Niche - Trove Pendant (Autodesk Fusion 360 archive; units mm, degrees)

design "Trove" references "Niche - Chief Architect - Luxe Single Pendant Cordset", "Luxe Single Pendant Cordset - 4ft Standard", "Trove"
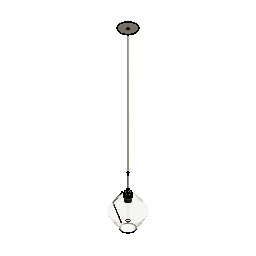
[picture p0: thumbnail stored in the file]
external_derived "ExternalDerived1" bodies "Trove"
external_derived "ExternalDerived2" bodies "Socket Body", "Shade Ring", "Shade Ring +Collar", "Socket", "Body1", "Metal Strain Relief", "Fabric Cord (1)", "Stem (Threaded)"
align "Align1"
external_derived "ExternalDerived3" bodies "T9-Bulb"
move "Move1"
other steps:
derived_base_feature "Derived Base Feature1" bodies "Trove"
derived_base_feature "Derived Base Feature2" bodies "Socket Body", "Shade Ring", "Shade Ring +Collar", "Socket", "Body1", "Metal Strain Relief", "Fabric Cord (1)", "Stem (Threaded)"
derived_base_feature "Derived Base Feature3" bodies "T9-Bulb"
named bodies: "Trove", "Socket Body", "Shade Ring", "Shade Ring +Collar", "Socket", "Body1", "Metal Strain Relief", "Fabric Cord (1)", "Stem (Threaded)", "Cap (Threaded)", "5M Set Screw", "T9-Bulb"

design "Luxe Single Pendant Cordset - 4ft Standard" references "Luxe Canopy - Single Pendant Cordset"
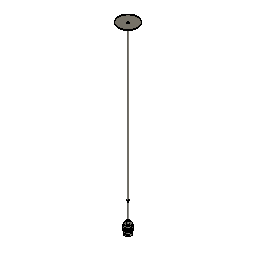
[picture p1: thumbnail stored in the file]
external_derived "ExternalDerived2" bodies "Cap (Threaded)"
move "Move1"
move "Move2"
offset_faces "OffsetFaces1" distance 1051.56
move "Move3"
move "Move4"
move "Move5"
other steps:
derived_base_feature "Derived Base Feature9" bodies "Socket Body", "Shade Ring", "Shade Ring +Collar", "Socket"
derived_base_feature "Derived Base Feature10" bodies "Body1"
derived_base_feature "Derived Base Feature12" bodies "Metal Strain Relief"
derived_base_feature "Derived Base Feature13" bodies "Fabric Cord (1)"
derived_base_feature "Derived Base Feature14" bodies "Stem (Threaded)"
derived_base_feature "Derived Base Feature15" bodies "Cap 9Threaded)", "Cap (Threaded)"
named bodies: "Socket Body", "Shade Ring", "Shade Ring +Collar", "Socket", "Metal Strain Relief", "Fabric Cord (1)", "Stem (Threaded)", "Cap 9Threaded)", "Body1", "Cap (Threaded)", "5M Set Screw"

design "Luxe Canopy - Single Pendant Cordset" references "M5 Set Screw", "Canopy Mounting Bar", "Plastic Strain Relief", "Canopy Mounting Bar Screw", "Luxe Cordset"
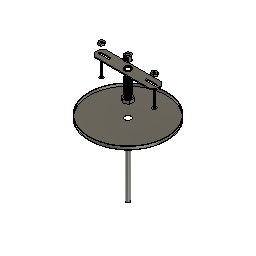
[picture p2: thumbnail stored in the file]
sketch "Sketch1" plane through (0, 0, 0) normal (0, 0, 1) x axis (1, 0, 0)
  circle C1 centre (0, 0) radius 63.5
  point P1 (0, 0)
  point P2 (0, 0)
  coincident P1 P2
  dimension "d1" diameter C1 = 127
extrude "Extrude1" new body sketch "Sketch1" along normal blind 5.08
shell "Shell1" innerThickness 0.762
hole "Hole1" HoleDepth 35.56 HoleDiameter 10.16 TipAngle 118
component_from_bodies "Body->Comp1"
component_insert "Component Insert1"
component_insert "Component Insert2"
component_insert "Component Insert3"
sketch "Sketch2" plane through (0, 0, 0) normal (0, 0, 1) x axis (1, 0, 0)
  circle C1 centre (0, 0) radius 3.175
  point P1 (0, 0)
  point P2 (0, 0)
  coincident P1 P2
  dimension "d8" diameter C1 = 6.35
extrude "Extrude2" new body sketch "Sketch2" along normal blind 127 and against normal blind 127 bodies "Fabric Cord"
component_insert "Component Insert4"
component_insert "Component Insert5"
position "Position1"
sketch "Sketch3" plane through (0, 0, 0.762) normal (0, 0, 1) x axis (-1, 0, 0)
  circle C1 centre (-0.0475, 0.2257) radius 5.08
  circle C2 centre (0, 0) radius 62.738
  circle C3 centre (0, 0) radius 4.826
  concentric C2 C3
  dimension "d13" diameter C3 = 9.652
extrude "Extrude3" new body sketch "Sketch3" profile of C3 along normal blind 25.4 bodies "Threaded Nipple"
shell "Shell2" innerThickness 1.27
thread "Thread1"
sketch "Sketch5" plane through (0, 0, 127) normal (0, 0, 1) x axis (-1, 0, 0)
  line L1 (-6.8191, 3.937) -> (0, 7.874)
  line L2 (-6.8191, -3.937) -> (-6.8191, 3.937)
  line L3 (0, -7.874) -> (-6.8191, -3.937)
  line L4 (6.8191, -3.937) -> (0, -7.874)
  line L5 (6.8191, 3.937) -> (6.8191, -3.937)
  line L6 (0, 7.874) -> (6.8191, 3.937)
  circle C1 centre (0, 0) radius 3.175
  point P2 (0, 0)
  point P9 (0, 0)
  point P3 (0, 7.874)
  coincident P2 P9
  dimension "d20" distance P3 P9 = 7.874
extrude "Extrude4" new body sketch "Sketch5" along normal blind 5.08 bodies "Hex Nut"
move "Move1"
thread "Thread2"
move "Move2" TranslateX 0 TranslateY 0 TranslateZ -55.88
move "Move3" TranslateX 0 TranslateY 0 TranslateZ 60.96
position "Position2"
sketch "Sketch6" plane through (0, 0, 0) normal (0, 0, 1) x axis (1, 0, 0)
  circle C1 centre (0, 0) radius 9.525
  point P1 (0, 0)
  point P2 (0, 0)
  coincident P1 P2
  dimension "d29" diameter C1 = 19.05
extrude "Extrude5" new body sketch "Sketch6" along normal blind 16.129 bodies "Metal Strain Relief"
move "Move4" TranslateX 0 TranslateY 0 TranslateZ -86.36
hole "Hole2" HoleDepth 10.16 HoleDiameter 5.08 TipAngle 118
hole "Hole3" HoleDepth 4.064 HoleDiameter 7.62 TipAngle 180
hole "Hole4" HoleDepth 12.192 HoleDiameter 9.144 TipAngle 180
thread "Thread3" ThreadOffset 0 ThreadLength 6.096
move "Move1" TranslateX 0 TranslateY 0 TranslateZ 68.58
move "Move5" TranslateX 0 TranslateY 0 TranslateZ 138.43
component_insert "Component Insert6"
external_derived "ExternalDerived1" bodies "5M Set Screw"
move "Move6" TranslateX 0 TranslateY 0 TranslateZ -185.42
copy_paste_bodies "CopyPasteBodies1"
move "Move7" TranslateX 0 TranslateY 0 TranslateZ -12.7
offset_faces "OffsetFaces1" distance -152.4
move "Move8"
component_from_bodies "Body->Comp2"
component_from_bodies "Body->Comp3"
component_from_bodies "Body->Comp4"
component_from_bodies "Body->Comp5"
hole "Hole1" HoleDepth 25.4 HoleDiameter 6.35 TipAngle 180
sketch "Sketch7" plane through (0, 0, 0) normal (0, 0, 1) x axis (1, 0, 0)
  line L1 (49.784, 3.9595) -> (52.07, 0)
  line L2 (45.212, 3.9595) -> (49.784, 3.9595)
  line L3 (42.926, 0) -> (45.212, 3.9595)
  line L4 (45.212, -3.9595) -> (42.926, 0)
  line L5 (49.784, -3.9595) -> (45.212, -3.9595)
  line L6 (52.07, 0) -> (49.784, -3.9595)
  point P2 (52.07, 0)
  point P8 (47.498, 0)
  dimension "d63" distance P2 P8 = 4.572
extrude "Extrude6" new body sketch "Sketch7" along normal blind 3.175 bodies "Mounting Hex Nut"
hole "Hole5" HoleDepth 25.4 HoleDiameter 3.81 TipAngle 180
thread "Thread4"
move "Move9"
component_from_bodies "Body->Comp6"
copy_paste "CopyPaste1"
move "Move10"
derived_base_feature "Derived Base Feature3" bodies "Stem (Threaded)", "Cap 9Threaded)"
move "Move11"
component_from_bodies "Body->Comp7"
component_from_bodies "Body->Comp8"
component_from_bodies "Body->Comp9"
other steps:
base_feature "Base Feature1"
base_feature "Base Feature1" bodies "Stem (Threaded)"
base_feature "Base Feature1" bodies "Cap 9Threaded)"
base_feature "Base Feature1" bodies "Fabric Cord"
base_feature "Base Feature1" bodies "Metal Strain Relief"
base_feature "Base Feature1" bodies "Mounting Hex Nut"
base_feature "Base Feature1" bodies "Hex Nut"
base_feature "Base Feature1" bodies "Fabric Cord (1)"
base_feature "Base Feature1" bodies "Threaded Nipple"
derived_base_feature "Derived Base Feature1" bodies "Socket Body", "Shade Ring", "Shade Ring +Collar", "Socket", "Rigid Stem"
derived_base_feature "Derived Base Feature2" bodies "5M Set Screw"
base_feature "Base Feature1" bodies "Fabric Cord", "Fabric Cord (1)"
create_component "CreateComponent1"
remove_body "RemoveBody1"
create_component "CreateComponent2"
remove_body "RemoveBody2"
create_component "CreateComponent3"
remove_body "RemoveBody3"
create_component "CreateComponent4"
remove_body "RemoveBody4"
create_component "CreateComponent5"
remove_body "RemoveBody5"
create_component "CreateComponent6"
remove_body "RemoveBody6"
create_component "CreateComponent7"
remove_body "RemoveBody7"
create_component "CreateComponent8"
remove_body "RemoveBody8"
create_component "CreateComponent9"
remove_body "RemoveBody9"
named bodies: "Fabric Cord", "Threaded Nipple", "Hex Nut", "Metal Strain Relief", "Socket Body", "Shade Ring", "Shade Ring +Collar", "Socket", "Rigid Stem", "5M Set Screw", "Fabric Cord (1)", "Mounting Hex Nut", "Stem (Threaded)", "Cap 9Threaded)"

design "M5 Set Screw"
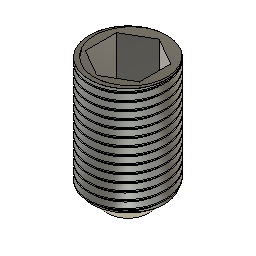
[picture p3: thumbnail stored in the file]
sketch "Sketch1" plane through (0, 0, 0) normal (0, 0, 1) x axis (1, 0, 0)
  circle C1 centre (0, 0) radius 2.5
  point P1 (0, 0)
  point P2 (0, 0)
  coincident P1 P2
  dimension "d1" diameter C1 = 5
extrude "Extrude1" new body sketch "Sketch1" along normal blind 8
sketch "Sketch2" plane through (0, 0, 8) normal (0, 0, 1) x axis (-1, 0, 0)
  line L1 (-1.7321, 1) -> (0, 2)
  line L2 (-1.7321, -1) -> (-1.7321, 1)
  line L3 (0, -2) -> (-1.7321, -1)
  line L4 (1.7321, -1) -> (0, -2)
  line L5 (1.7321, 1) -> (1.7321, -1)
  line L6 (0, 2) -> (1.7321, 1)
  circle C1 centre (0, 0) radius 2.5
  point P2 (0, 0)
  point P9 (0, 0)
  coincident P2 P9
extrude "Extrude2" cut sketch "Sketch2" profile of L1 L2 L3 L4 L5 L6 against normal blind 3
thread "Thread1" ThreadOffset 0.99 ThreadLength 7
chamfer "Chamfer1" distance 1.15

design "Luxe Cordset" references "M5 Set Screw"
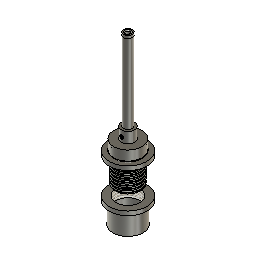
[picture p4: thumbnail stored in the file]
sketch "Sketch1" plane through (0, 0, 0) normal (0, 0, 1) x axis (1, 0, 0)
  circle C1 centre (0, 0) radius 20.6
  point P1 (0, 0)
  point P2 (0, 0)
  coincident P1 P2
  dimension "d11" diameter C1 = 41.2
extrude "Extrude1" new body sketch "Sketch1" along normal blind 14 bodies "Socket Body"
sketch "Sketch2" plane through (0, 0, 14) normal (0, 0, 1) x axis (-1, 0, 0)
  circle C1 centre (0, 0) radius 20.6
  circle C2 centre (0, 0) radius 9.6
  concentric C1 C2
  dimension "d3" diameter C2 = 19.2
extrude "Extrude2" add sketch "Sketch2" profile of C2 along normal blind 15.75
sketch "Sketch3" plane through (0, 0, 29.75) normal (0, 0, 1) x axis (-1, 0, 0)
  circle C1 centre (0, 0) radius 9.6
  circle C2 centre (0, 0) radius 5.75
  concentric C1 C2
  dimension "d6" diameter C2 = 11.5
extrude "Extrude3" new body sketch "Sketch3" profile of C2 along normal blind 114 bodies "Rigid Stem"
move "Move1"
sketch "Sketch4" plane through (0, 0, 203.75) normal (0, 0, 1) x axis (-1, 0, 0)
  circle C1 centre (0, 0) radius 5.75
  circle C2 centre (0, 0) radius 27.5
  dimension "d10" diameter C2 = 55
extrude "Extrude4" new body sketch "Sketch4" profile of C2 along normal blind 6 bodies "Shade Ring"
hole "Hole1" HoleDepth 25 HoleDiameter 42.75 TipAngle 118
sketch "Sketch5" plane through (0, 0, 0) normal (0, 0, 1) x axis (1, 0, 0)
  circle C1 centre (0, 0) radius 22
  point P1 (0, 0)
  point P2 (0, 0)
  coincident P1 P2
  dimension "d18" diameter C1 = 44
move "Move2"
copy_paste_bodies "CopyPasteBodies1"
move "Move3"
sketch "Sketch6" plane through (0, 0, 60) normal (0, 0, -1) x axis (1, 0, 0)
  circle C1 centre (0, 0) radius 20.6
  circle C2 centre (0, 0) radius 21.375
  circle C3 centre (0, 0) radius 20
  concentric C1 C2
  concentric C1 C3
  dimension "d21" diameter C2 = 42.75
  dimension "d24" diameter C3 = 40
cylinder_primitive "CylinderPrimitive1" Height 8 Diameter 42.75
thread "Thread1"
thread "Thread3"
hole "Hole2" HoleDepth 18 HoleDiameter 39 TipAngle 180
move "Move4"
move "Move5"
move "Move6"
hole "Hole3" HoleDepth 114 HoleDiameter 7.6 TipAngle 180
derived_base_feature "Derived Base Feature" bodies "Socket"
move "Move7"
scale "Scale1" ScaleX 1.2 ScaleY 1.2
move "Move8"
sketch "Sketch8" plane through (0, 0, -23.9827) normal (0, 0, -1) x axis (1, 0, 0)
  circle C1 centre (0, -0.036) radius 27.5
  circle C2 centre (0, -0.036) radius 22
  circle C3 centre (0, -0.036) radius 19.5
  dimension "d36" diameter C2 = 44
  dimension "d42" = -2.5
extrude "Extrude7" add sketch "Sketch8" profile of C2 C3 along normal blind 30
offset_faces "OffsetFaces1" distance 2.75
offset_faces "OffsetFaces2" distance -9
thread "Thread2"
move "Move9"
move "Move10"
move "Move11"
scale "Scale2" ScaleZ 1.2
move "Move12"
move "Move13"
move "Move14"
move "Move15"
move "Move16"
split_face "SplitFace1"
move "Move17"
move "Move18"
move "Move19"
move "Move20"
move "Move21"
move "Move22"
move "Move23"
move "Move24"
move "Move25"
move "Move26"
move "Move27"
thread "Thread4"
move "Move28"
move "Move29"
move "Move30"
hole "Hole4" HoleDepth 21 HoleDiameter 39.35 TipAngle 180
hole "Hole5" HoleDepth 9 HoleDiameter 5 TipAngle 180
move "Move31"
move "Move32"
hole "Hole6" HoleDepth 20 HoleDiameter 10 TipAngle 180
move_face "MoveFace3"
move "Move33"
move "Move34"
move "Move35"
move "Move36"
move "Move37"
thread "Thread5" ThreadOffset 0 ThreadLength 6
thread "Thread6" ThreadOffset 0 ThreadLength 6
move "Move38"
move "Move39"
move "Move40"
move "Move41"
component_insert "Component Insert"
thread "Thread7" ThreadOffset 0.5 ThreadLength 5.337
chamfer "Chamfer1" distance 0.5 distance 0.35
sketch "Sketch12" plane through (0, 0, 0) normal (0, 0, 1) x axis (1, 0, 0)
  circle C1 centre (0, 0) radius 6.35
  dimension "d60" diameter C1 = 12.7
extrude "Extrude8" new body sketch "Sketch12" along normal blind 115 bodies "Stem (Threaded)"
hole "Hole7" HoleDepth 115 HoleDiameter 9.65 TipAngle 118
thread "Thread8" ThreadOffset 0 ThreadLength 12.5
thread "Thread9" ThreadOffset 0 ThreadLength 12.5
sketch "Sketch13" plane through (0, 0, 0) normal (0, 0, 1) x axis (1, 0, 0)
  circle C1 centre (0, 0) radius 6.35
  point P1 (0, 0)
  point P2 (0, 0)
  coincident P1 P2
  dimension "d70" diameter C1 = 12.7
extrude "Extrude9" new body sketch "Sketch13" along normal blind 4 bodies "Cap 9Threaded)"
sketch "Sketch14" plane through (0, 0, 4) normal (0, 0, 1) x axis (-1, 0, 0)
  circle C1 centre (0, 0) radius 6.35
  circle C2 centre (0, 0) radius 4.5
  concentric C1 C2
  dimension "d73" diameter C2 = 9
extrude "Extrude10" add sketch "Sketch14" profile of C2 against normal blind 14
thread "Thread10"
hole "Hole8" HoleDepth 115 HoleDiameter 6.5 TipAngle 118 CSDiameter 9 CSAngle 90
move "Move42"
move "Move43"
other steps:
base_feature "Base Feature" bodies "Shade Ring +Collar"
named bodies: "Socket Body", "Shade Ring", "Shade Ring +Collar", "Socket", "Rigid Stem", "Stem (Threaded)", "Cap 9Threaded)"

design "Plastic Strain Relief"
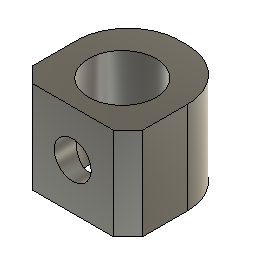
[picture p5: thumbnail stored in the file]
base_feature "Base Feature" bodies "strainrelief"
named bodies: "strainrelief"

design "Trove" references "Niche_Trove_Single_Pendant"
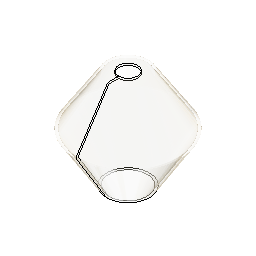
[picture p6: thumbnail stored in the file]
external_derived "ExternalDerived" bodies "Trove"
hole "Hole1" HoleDepth 88.9 HoleDiameter 44.45 TipAngle 118
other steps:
derived_base_feature "Derived Base Feature" bodies "Trove"
named bodies: "Trove"

design "Niche_Trove_Single_Pendant"
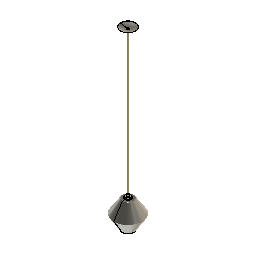
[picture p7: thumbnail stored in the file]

design "Canopy Mounting Bar Screw"
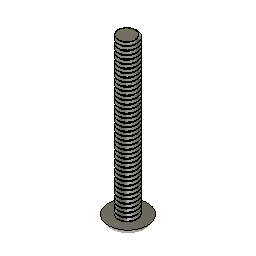
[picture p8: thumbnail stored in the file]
base_feature "Base Feature" bodies "screw1"
named bodies: "screw1"

design "Canopy Mounting Bar"
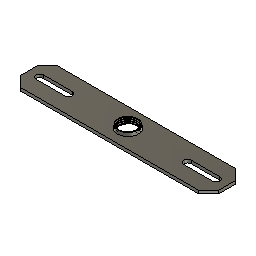
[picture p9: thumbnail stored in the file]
base_feature "Base Feature" bodies "mountingbar"
named bodies: "mountingbar"

design "Niche - Chief Architect - Luxe Single Pendant Cordset"
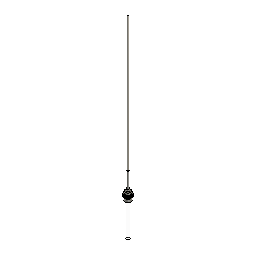
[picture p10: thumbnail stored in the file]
derived_base_feature "Derived Base Feature" bodies "Socket Body", "Shade Ring", "Shade Ring +Collar", "Socket", "Canopy", "Metal Strain Relief", "Fabric Cord (1)", "Stem (Threaded)"
remove_body "RemoveBody1"
remove_body "RemoveBody2"
split "Split1" bodies "Socket Body (1)"
remove_body "RemoveBody3"
align "Align1"
hole "Hole1" HoleDepth 19.05 HoleDiameter 8.89 TipAngle 118
combine "Combine1" bodies "Shade Ring"
split "Split2" bodies "Socket (1)"
remove_body "RemoveBody4"
split "Split3" bodies "Fabric Cord (1) (1)"
remove_body "RemoveBody5"
combine "Combine2" bodies "Socket Body"
align "Align2"
combine "Combine3" bodies "Metal Strain Relief"
sketch "Sketch1" plane through (0, 0, 0) normal (0, 1, 0) x axis (1, 0, 0)
  line L1 (13.1098, 24.9049) -> (-12.2902, 24.9049)
  line L2 (18.1898, 37.1766) -> (18.1898, 29.9849)
  line L3 (-17.3702, 29.9849) -> (-17.3702, 36.7132)
  line L4 (0, 132.969) -> (0, 24.9049)
  arc A1 centre (0, 86.36) radius 46.609 clockwise from (-22.6031, 45.5985) to (23.276, 45.979)
  arc A2 centre (-27.5302, 36.7132) radius 10.16 clockwise from (-22.6031, 45.5985) to (-17.3702, 36.7132)
  arc A3 centre (28.3498, 37.1766) radius 10.16 clockwise from (18.1898, 37.1766) to (23.276, 45.979)
  arc A4 centre (-12.2902, 29.9849) radius 5.08 clockwise from (-12.2902, 24.9049) to (-17.3702, 29.9849)
  arc A5 centre (13.1098, 29.9849) radius 5.08 clockwise from (18.1898, 29.9849) to (13.1098, 24.9049)
  point P5 (18.1898, 43.4469)
  point P3 (-17.3702, 24.9049)
  point P4 (18.1898, 24.9049)
  point P18 (0, 24.9049)
  point P19 (0, 132.969)
  horizontal L1
  vertical L2
  vertical L3
  tangent A1 A2
  tangent L3 A2
  coincident P5 L2
  coincident P5 A1
  tangent L2 A3
  tangent A1 A3
  equal A2 A3
  coincident P3 L1
  coincident P3 L3
  tangent L1 A4
  tangent L3 A4
  coincident P4 L1
  coincident P4 L2
  tangent L1 A5
  tangent L2 A5
  coincident L1 P18
  coincident A1 P19
  perpendicular L1 L4
  dimension "d4" diameter A1 = 93.218
  dimension "d5" distance P3 P4 = 35.56
  dimension "d6" distance P4 P5 = 18.542
  dimension "d7" radius A2 = 10.16
  dimension "d8" radius A4 = 5.08
  dimension "d9" radius A5 = 5.08
revolve "Revolve1" sketch "Sketch1" AlongAngle 360 bodies "G30-Bulb"
move "Move1"
sketch "Sketch2" plane through (0, 0, 0) normal (0, 1, 0) x axis (1, 0, 0)
  line L1 (12.7, 0) -> (-12.7, 0)
  line L2 (12.7, 152.4) -> (12.7, 0)
  line L3 (-12.7, 0) -> (-12.7, 152.4)
  line L4 (0, 165.1) -> (0, 0)
  arc A1 centre (0, 152.4) radius 12.7 clockwise from (-12.7, 152.4) to (12.7, 152.4)
  point P1 (0, 0)
  point P7 (0, 0)
  point P8 (0, 165.1)
  horizontal L1
  vertical L2
  vertical L3
  coincident P1 P7
  midpoint A1 P8
  perpendicular L1 L4
revolve "Revolve2" sketch "Sketch2" AlongAngle 360 bodies "T9-Bulb"
move "Move2"
sketch "Sketch3" plane through (0, 0, 0) normal (0, 1, 0) x axis (1, 0, 0)
  line L1 (12.7, 0) -> (-12.7, 0)
  line L2 (12.7, 254) -> (12.7, 0)
  line L3 (-12.7, 0) -> (-12.7, 254)
  line L4 (0, 266.7) -> (0, 0)
  arc A1 centre (0, 254) radius 12.7 clockwise from (-12.7, 254) to (12.7, 254)
  point P1 (0, 0)
  point P7 (0, 0)
  point P8 (0, 266.7)
  horizontal L1
  vertical L2
  vertical L3
  coincident P1 P7
  midpoint A1 P8
  perpendicular L1 L4
revolve "Revolve3" sketch "Sketch3" AlongAngle 360 bodies "T8-Bulb"
move "Move3"
move "Move4"
move "Move5"
sketch "Sketch4" plane through (0, 0, 0) normal (0, 1, 0) x axis (1, 0, 0)
  line L1 (15.875, -8.763) -> (-15.875, -8.763)
  line L2 (15.875, 22.987) -> (15.875, -8.763)
  line L3 (-15.875, 22.987) -> (15.875, 22.987)
  line L4 (-15.875, -8.763) -> (-15.875, 22.987)
  line L5 (0, 22.987) -> (0, -8.763)
  point P6 (0, -8.763)
  point P7 (0, 22.987)
  point P2 (-15.875, -8.763)
  point P3 (15.875, -8.763)
  point P5 (-15.875, 22.987)
  horizontal L1
  vertical L2
  horizontal L3
  vertical L4
  midpoint L1 P6
  midpoint L3 P7
  dimension "d13" distance P2 P3 = 31.75
  dimension "d14" distance P2 P5 = 31.75
revolve "Revolve4" sketch "Sketch4" AlongAngle 360 bodies "Bulb Extender"
move "Move6"
sketch "Sketch5" plane through (0, 0, 0) normal (0, 1, 0) x axis (1, 0, 0)
  line L1 (-12.7, 35.56) -> (12.7, 35.56)
  line L2 (-12.7, 5.08) -> (-12.7, 35.56)
  line L3 (12.7, 5.08) -> (-12.7, 5.08)
  line L4 (12.7, 35.56) -> (12.7, 5.08)
  line L5 (-12.7, 5.08) -> (12.7, 35.56)
  line L6 (12.7, 5.08) -> (-12.7, 35.56)
  line L7 (0, 35.56) -> (0, 5.08)
  point P6 (0, 20.32)
  point P7 (0, 5.08)
  point P8 (0, 35.56)
  horizontal L1
  perpendicular L1 L2
  parallel L1 L3
  parallel L2 L4
  coincident L5 P6
  coincident L6 P6
  midpoint L3 P7
  midpoint L1 P8
revolve "Revolve5" sketch "Sketch5" AlongAngle 360 bodies "Y-Spliter"
sketch "Sketch6" plane through (0, 0, 0) normal (0, 1, 0) x axis (1, 0, 0)
  line L1 (-55.88, 64.9514) -> (-21.59, 64.9514)
  line L2 (-55.88, 35.7414) -> (-55.88, 64.9514)
  line L3 (-21.59, 35.7414) -> (-55.88, 35.7414)
  line L4 (-21.59, 64.9514) -> (-21.59, 35.7414)
  line L5 (-55.88, 35.7414) -> (-21.59, 64.9514)
  line L6 (-21.59, 35.7414) -> (-55.88, 64.9514)
  line L7 (-38.735, 64.9514) -> (-38.735, 35.7414)
  point P6 (-38.735, 50.3464)
  point P7 (-38.735, 35.7414)
  point P8 (-38.735, 64.9514)
  point P4 (-55.88, 35.7414)
  point P5 (-21.59, 35.7414)
  point P2 (-21.59, 64.9514)
  horizontal L1
  perpendicular L1 L2
  parallel L1 L3
  parallel L2 L4
  coincident L5 P6
  coincident L6 P6
  midpoint L3 P7
  midpoint L1 P8
  dimension "d17" distance P4 P5 = 34.29
  dimension "d18" distance P2 P5 = 29.21
revolve "Revolve6" sketch "Sketch6" AlongAngle 360
chamfer "Chamfer1" distance 7.62
move "Move7"
mirror "Mirror1" mirrorStitchTolerance 0.1016
move "Move8"
combine "Combine4"
move "Move9"
sketch "Sketch7" plane through (0, 0, 0) normal (0, 1, 0) x axis (1, 0, 0)
  line L1 (-15.24, 40.64) -> (-15.24, 48.1816)
  line L2 (12.7, 38.1) -> (-12.7, 38.1)
  line L3 (15.24, 48.1816) -> (15.24, 40.64)
  line L4 (0, 100.1623) -> (0, 38.1)
  arc A1 centre (0, 76.2) radius 23.9623 clockwise from (-19.7282, 62.5988) to (19.7282, 62.5988)
  arc A2 centre (-40.64, 48.1816) radius 25.4 clockwise from (-19.7282, 62.5988) to (-15.24, 48.1816)
  arc A3 centre (40.64, 48.1816) radius 25.4 clockwise from (15.24, 48.1816) to (19.7282, 62.5988)
  arc A4 centre (-12.7, 40.64) radius 2.54 clockwise from (-12.7, 38.1) to (-15.24, 40.64)
  arc A5 centre (12.7, 40.64) radius 2.54 clockwise from (15.24, 40.64) to (12.7, 38.1)
  point P15 (0, 38.1)
  point P16 (0, 100.1623)
  parallel L1 L3
  tangent A1 A2
  tangent L1 A2
  tangent A1 A3
  tangent L3 A3
  tangent L1 A4
  tangent L2 A4
  tangent L2 A5
  tangent L3 A5
  midpoint L2 P15
  midpoint A1 P16
  perpendicular L2 L4
  dimension "d23" radius A2 = 25.4
  dimension "d24" radius A3 = 25.4
  dimension "d25" radius A4 = 2.54
  dimension "d26" radius A5 = 2.54
revolve "Revolve7" sketch "Sketch7" AlongAngle 360 bodies "A15-Bulb"
move "Move10"
copy_paste_bodies "CopyPasteBodies1"
copy_paste_bodies "CopyPasteBodies2"
move "Move11"
mirror "Mirror2" mirrorStitchTolerance 0.1016 bodies "A15-Bulb (1) (1)"
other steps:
base_feature "Base Feature1" bodies "Y-Spliter", "Bulb Extender", "Y-Spliter (1)", "Bulb Extender (1)"
base_feature "Base Feature2" bodies "A15-Bulb", "A15-Bulb (1)"
named bodies: "Socket Body", "Shade Ring", "Shade Ring +Collar", "Socket", "Canopy", "Metal Strain Relief", "Fabric Cord (1)", "Stem (Threaded)", "Adapter", "5M Set Screw", "Body1 (1)", "Socket Body (1)", "Socket (1)", "Fabric Cord (1) (1)", "G30-Bulb", "T9-Bulb", "T8-Bulb", "Bulb Extender", "Y-Spliter", "A15-Bulb", "Y-Spliter (1)", "Bulb Extender (1)", "A15-Bulb (1)", "A15-Bulb (1) (1)"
